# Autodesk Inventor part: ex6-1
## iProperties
Author: Administrator
Created: 2001-09
Part Number: ex6-1
Document SubType Name: Modeling
Designer: Administrator
Control State: 0
Master: False
Checked Out: False
PropertySet Name: Design Tracking Control
Length Units: 11272
Angle Units: 11279
Time Units: 11290
Mass Units: 11286
Shininess: 3
Angle Display Precision: 2
Document Length Units: 11272
Document Angle Units: 11286
Document Time Units: 11279
Document Mass Units: 11290
Document Length Units Precision: 3
Document Angle Units Precision: 2
Compacted: False
PropertySet Name: _Private Model Information
Density: 0.0
Volumn: 0.0
Area: 0.0
PropertySet Name: Model Information
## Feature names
1. Extrusion1
2. Extrusion2
3. Extrusion3
